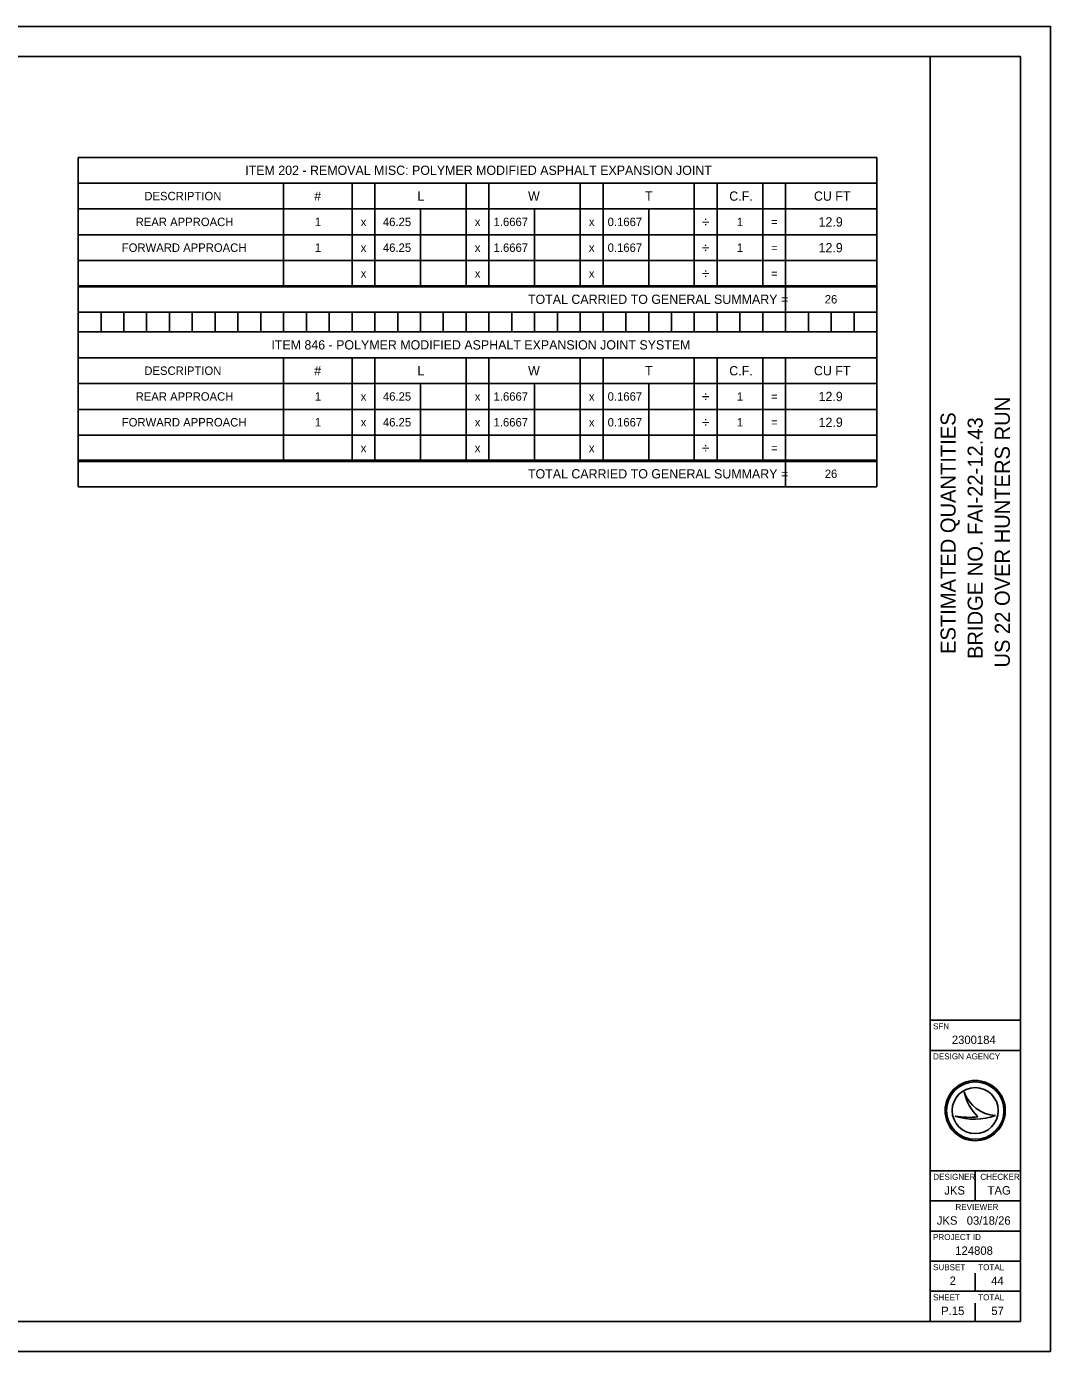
# Model space of a CAD drawing. Extents: x 0 to 34, y 0 to 22.
# Drawn here: x 17 to 34, y 0 to 22 of the extents above; entities that cross this region are included whole.
import ezdxf

# ---------------------------------------------------------------- set-up
doc = ezdxf.new("R2010")
doc.units = 0
for name, color, linetype in [('SH_Border', 7, 'Continuous'), ('SH_Cut_Line', 7, 'Continuous'), ('SH_Data', 7, 'Continuous'), ('SH_Text', 7, 'Continuous')]:
    doc.layers.add(name, color=color, linetype=linetype)

msp = doc.modelspace()

# ---------------------------------------------------------------- linework, layer by layer
at = {"layer": 'SH_Border'}
for p, q in [((32, 0.5), (32, 21.5)), ((32, 5.5), (33.5, 5.5)), ((32, 5), (33.5, 5)), ((32, 3), (33.5, 3)), ((32.75, 3), (32.75, 2.5)), ((32, 2.5), (33.5, 2.5)), ((32, 2), (33.5, 2)), ((32, 1.5), (33.5, 1.5)), ((32, 1), (33.5, 1))]:
    msp.add_line(p, q, dxfattribs=at)
msp.add_lwpolyline([(1.5, 21.5), (33.5, 21.5), (33.5, 0.5), (1.5, 0.5)], close=True, dxfattribs=at)
at = {"layer": 'SH_Cut_Line'}
msp.add_lwpolyline([(0, 0), (34, 0), (34, 22), (0, 22)], close=True, dxfattribs=at)
at = {"layer": 'SH_Data'}
for p, q in [((32.567, 4.31), (32.567, 4.31)), ((32.75, 4), (32.75, 4)), ((32.417, 3.91), (32.417, 3.91)), ((33.087, 3.919), (33.087, 3.919)), ((32.75, 1), (32.75, 1.3)), ((32.375, 0.675), (32.375, 0.675)), ((32.75, 0.5), (32.75, 0.8))]:
    msp.add_line(p, q, dxfattribs=at)
for radius in [0.5, 0.477, 0.477, 0.382]:
    msp.add_circle((32.75, 4), radius, dxfattribs=at)
for centre, radius, start, end in [((33.116, 4.498), 0.58, 198.9257, 198.9319), ((33.347, 4.47), 0.796, 191.6379, 191.6421), ((33.116, 4.498), 0.58, 198.9319, 267.1657), ((33.347, 4.47), 0.796, 191.6421, 226.0947), ((32.739, 4.87), 1.013, 251.4576, 290.0832), ((32.648, 5.154), 1.266, 259.4964, 259.4995), ((32.739, 4.87), 1.013, 251.4527, 251.4576), ((32.648, 5.154), 1.266, 259.4995, 276.6672)]:
    msp.add_arc(centre, radius, start, end, dxfattribs=at)
at = {"layer": 'SH_Text'}
for p, q in [((17.858, 19.827), (31.117, 19.827)), ((17.858, 19.827), (17.858, 17.675)), ((31.117, 19.827), (31.117, 17.675)), ((17.858, 19.398), (31.117, 19.398)), ((21.267, 19.398), (21.267, 17.696)), ((22.404, 19.398), (22.404, 17.696)), ((22.783, 19.398), (22.783, 17.696)), ((24.298, 19.398), (24.298, 17.696)), ((24.677, 19.398), (24.677, 17.696)), ((26.192, 19.398), (26.192, 17.696)), ((26.571, 19.398), (26.571, 17.696)), ((28.086, 19.398), (28.086, 17.696)), ((28.465, 19.398), (28.465, 17.696)), ((29.223, 19.398), (29.223, 17.696)), ((29.602, 19.398), (29.602, 17.696)), ((17.858, 18.97), (31.117, 18.97)), ((23.54, 18.97), (23.54, 17.696)), ((25.434, 18.97), (25.434, 17.696)), ((27.329, 18.97), (27.329, 17.696)), ((17.858, 18.542), (31.117, 18.542)), ((17.858, 18.114), (31.117, 18.114)), ((17.858, 17.696), (31.117, 17.696)), ((17.858, 17.696), (17.858, 14.776)), ((17.858, 17.675), (31.117, 17.675)), ((29.602, 17.675), (29.602, 17.257)), ((31.117, 17.696), (31.117, 14.776)), ((17.858, 17.257), (31.117, 17.257)), ((17.858, 16.928), (31.117, 16.928)), ((17.858, 16.5), (31.117, 16.5)), ((21.267, 16.5), (21.267, 14.798)), ((22.404, 16.5), (22.404, 14.798)), ((22.783, 16.5), (22.783, 14.798)), ((24.298, 16.5), (24.298, 14.798)), ((24.677, 16.5), (24.677, 14.798)), ((26.192, 16.5), (26.192, 14.798)), ((26.571, 16.5), (26.571, 14.798)), ((28.086, 16.5), (28.086, 14.798)), ((28.465, 16.5), (28.465, 14.798)), ((29.223, 16.5), (29.223, 14.798)), ((29.602, 16.5), (29.602, 14.798)), ((17.858, 16.071), (31.117, 16.071)), ((23.54, 16.071), (23.54, 14.798)), ((25.434, 16.071), (25.434, 14.798)), ((27.329, 16.071), (27.329, 14.798)), ((17.858, 15.643), (31.117, 15.643)), ((17.858, 15.215), (31.117, 15.215)), ((17.858, 14.798), (31.117, 14.798)), ((17.858, 14.798), (17.858, 14.358)), ((17.858, 14.776), (31.117, 14.776)), ((29.602, 14.776), (29.602, 14.358)), ((31.117, 14.798), (31.117, 14.358)), ((17.858, 14.358), (31.117, 14.358))]:
    msp.add_line(p, q, dxfattribs=at)
for points in [[(17.858, 17.257), (18.237, 17.257), (18.237, 16.928), (17.858, 16.928)], [(18.237, 17.257), (18.616, 17.257), (18.616, 16.928), (18.237, 16.928)], [(18.616, 17.257), (18.994, 17.257), (18.994, 16.928), (18.616, 16.928)], [(18.994, 17.257), (19.373, 17.257), (19.373, 16.928), (18.994, 16.928)], [(19.373, 17.257), (19.752, 17.257), (19.752, 16.928), (19.373, 16.928)], [(19.752, 17.257), (20.131, 17.257), (20.131, 16.928), (19.752, 16.928)], [(20.131, 17.257), (20.51, 17.257), (20.51, 16.928), (20.131, 16.928)], [(20.51, 17.257), (20.889, 17.257), (20.889, 16.928), (20.51, 16.928)], [(20.889, 17.257), (21.267, 17.257), (21.267, 16.928), (20.889, 16.928)], [(21.267, 17.257), (21.646, 17.257), (21.646, 16.928), (21.267, 16.928)], [(21.646, 17.257), (22.025, 17.257), (22.025, 16.928), (21.646, 16.928)], [(22.025, 17.257), (22.404, 17.257), (22.404, 16.928), (22.025, 16.928)], [(22.404, 17.257), (22.783, 17.257), (22.783, 16.928), (22.404, 16.928)], [(22.783, 17.257), (23.162, 17.257), (23.162, 16.928), (22.783, 16.928)], [(23.162, 17.257), (23.54, 17.257), (23.54, 16.928), (23.162, 16.928)], [(23.54, 17.257), (23.919, 17.257), (23.919, 16.928), (23.54, 16.928)], [(23.919, 17.257), (24.298, 17.257), (24.298, 16.928), (23.919, 16.928)], [(24.298, 17.257), (24.677, 17.257), (24.677, 16.928), (24.298, 16.928)], [(24.677, 17.257), (25.056, 17.257), (25.056, 16.928), (24.677, 16.928)], [(25.056, 17.257), (25.434, 17.257), (25.434, 16.928), (25.056, 16.928)], [(25.434, 17.257), (25.813, 17.257), (25.813, 16.928), (25.434, 16.928)], [(25.813, 17.257), (26.192, 17.257), (26.192, 16.928), (25.813, 16.928)], [(26.192, 17.257), (26.571, 17.257), (26.571, 16.928), (26.192, 16.928)], [(26.571, 17.257), (26.95, 17.257), (26.95, 16.928), (26.571, 16.928)], [(26.95, 17.257), (27.329, 17.257), (27.329, 16.928), (26.95, 16.928)], [(27.329, 17.257), (27.707, 17.257), (27.707, 16.928), (27.329, 16.928)], [(27.707, 17.257), (28.086, 17.257), (28.086, 16.928), (27.707, 16.928)], [(28.086, 17.257), (28.465, 17.257), (28.465, 16.928), (28.086, 16.928)], [(28.465, 17.257), (28.844, 17.257), (28.844, 16.928), (28.465, 16.928)], [(28.844, 17.257), (29.223, 17.257), (29.223, 16.928), (28.844, 16.928)], [(29.223, 17.257), (29.602, 17.257), (29.602, 16.928), (29.223, 16.928)], [(29.602, 17.257), (29.98, 17.257), (29.98, 16.928), (29.602, 16.928)], [(29.98, 17.257), (30.359, 17.257), (30.359, 16.928), (29.98, 16.928)], [(30.359, 17.257), (30.738, 17.257), (30.738, 16.928), (30.359, 16.928)], [(30.738, 17.257), (31.117, 17.257), (31.117, 16.928), (30.738, 16.928)]]:
    msp.add_lwpolyline(points, close=True, dxfattribs=at)

# ---------------------------------------------------------------- texts
at = {"layer": 'SH_Data'}
for s, p in [('US 22 OVER HUNTERS RUN', (33.325, 11.356)), ('ESTIMATED QUANTITIES', (32.425, 11.582)), ('BRIDGE NO. FAI-22-12.43', (32.875, 11.498))]:
    msp.add_text(s, height=0.25, rotation=90, dxfattribs=at).set_placement(p)
for s, height, p in [('SFN', 0.1, (32.05, 5.35)), ('2300184', 0.14, (32.362, 5.105)), ('DESIGN AGENCY', 0.1, (32.05, 4.85)), ('DESIGNER', 0.1, (32.054, 2.85)), ('CHECKER', 0.1, (32.835, 2.85)), ('JKS', 0.14, (32.237, 2.605)), ('TAG', 0.14, (32.955, 2.605)), ('REVIEWER', 0.1, (32.422, 2.35)), ('JKS', 0.14, (32.112, 2.105)), ('03/18/26', 0.14, (32.609, 2.105)), ('PROJECT ID', 0.1, (32.05, 1.85)), ('124808', 0.14, (32.419, 1.605)), ('SUBSET', 0.1, (32.05, 1.35)), ('TOTAL', 0.1, (32.8, 1.35)), ('2', 0.14, (32.325, 1.105)), ('44', 0.14, (33.016, 1.105)), ('SHEET', 0.1, (32.05, 0.85)), ('TOTAL', 0.1, (32.8, 0.85)), ('P.15', 0.14, (32.185, 0.605)), ('57', 0.14, (33.018, 0.605))]:
    msp.add_text(s, height=height, dxfattribs=at).set_placement(p)
at = {"layer": 'SH_Text'}
for s, height, p in [('ITEM 202 - REMOVAL MISC: POLYMER MODIFIED ASPHALT EXPANSION JOINT', 0.154, (20.631, 19.536)), ('DESCRIPTION', 0.14, (18.956, 19.114)), ('#', 0.154, (21.777, 19.107)), ('L', 0.154, (23.49, 19.107)), ('W', 0.154, (25.327, 19.107)), ('T', 0.154, (27.269, 19.107)), ('C.F.', 0.154, (28.667, 19.107)), ('CU FT', 0.154, (30.073, 19.107)), ('REAR APPROACH', 0.14, (18.812, 18.686)), ('1', 0.14, (21.786, 18.686)), ('x', 0.14, (22.548, 18.686)), ('46.25', 0.14, (22.917, 18.686)), ('x', 0.14, (24.442, 18.686)), ('1.6667', 0.14, (24.754, 18.686)), ('x', 0.14, (26.336, 18.686)), ('0.1667', 0.14, (26.648, 18.686)), ('÷', 0.168, (28.214, 18.672)), ('1', 0.14, (28.794, 18.686)), ('=', 0.14, (29.362, 18.686)), ('12.9', 0.154, (30.15, 18.679)), ('FORWARD APPROACH', 0.14, (18.582, 18.258)), ('1', 0.14, (21.786, 18.258)), ('x', 0.14, (22.548, 18.258)), ('46.25', 0.14, (22.917, 18.258)), ('x', 0.14, (24.442, 18.258)), ('1.6667', 0.14, (24.754, 18.258)), ('x', 0.14, (26.336, 18.258)), ('0.1667', 0.14, (26.648, 18.258)), ('÷', 0.168, (28.214, 18.244)), ('1', 0.14, (28.794, 18.258)), ('=', 0.14, (29.362, 18.258)), ('12.9', 0.154, (30.15, 18.251)), ('x', 0.14, (22.548, 17.83)), ('x', 0.14, (24.442, 17.83)), ('x', 0.14, (26.336, 17.83)), ('÷', 0.168, (28.214, 17.816)), ('=', 0.14, (29.362, 17.83)), ('TOTAL CARRIED TO GENERAL SUMMARY =', 0.154, (25.325, 17.394)), ('26', 0.14, (30.252, 17.401)), ('ITEM 846 - POLYMER MODIFIED ASPHALT EXPANSION JOINT SYSTEM', 0.154, (21.065, 16.637)), ('DESCRIPTION', 0.14, (18.956, 16.215)), ('#', 0.154, (21.777, 16.208)), ('L', 0.154, (23.49, 16.208)), ('W', 0.154, (25.327, 16.208)), ('T', 0.154, (27.269, 16.208)), ('C.F.', 0.154, (28.667, 16.208)), ('CU FT', 0.154, (30.073, 16.208)), ('REAR APPROACH', 0.14, (18.812, 15.787)), ('1', 0.14, (21.786, 15.787)), ('x', 0.14, (22.548, 15.787)), ('46.25', 0.14, (22.917, 15.787)), ('x', 0.14, (24.442, 15.787)), ('1.6667', 0.14, (24.754, 15.787)), ('x', 0.14, (26.336, 15.787)), ('0.1667', 0.14, (26.648, 15.787)), ('÷', 0.168, (28.214, 15.773)), ('1', 0.14, (28.794, 15.787)), ('=', 0.14, (29.362, 15.787)), ('12.9', 0.154, (30.15, 15.78)), ('FORWARD APPROACH', 0.14, (18.582, 15.359)), ('1', 0.14, (21.786, 15.359)), ('x', 0.14, (22.548, 15.359)), ('46.25', 0.14, (22.917, 15.359)), ('x', 0.14, (24.442, 15.359)), ('1.6667', 0.14, (24.754, 15.359)), ('x', 0.14, (26.336, 15.359)), ('0.1667', 0.14, (26.648, 15.359)), ('÷', 0.168, (28.214, 15.345)), ('1', 0.14, (28.794, 15.359)), ('=', 0.14, (29.362, 15.359)), ('12.9', 0.154, (30.15, 15.352)), ('x', 0.14, (22.548, 14.931)), ('x', 0.14, (24.442, 14.931)), ('x', 0.14, (26.336, 14.931)), ('÷', 0.168, (28.214, 14.917)), ('=', 0.14, (29.362, 14.931)), ('TOTAL CARRIED TO GENERAL SUMMARY =', 0.154, (25.325, 14.496)), ('26', 0.14, (30.252, 14.503))]:
    msp.add_text(s, height=height, dxfattribs=at).set_placement(p)

doc.saveas('drawing.dxf')
